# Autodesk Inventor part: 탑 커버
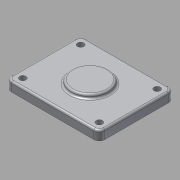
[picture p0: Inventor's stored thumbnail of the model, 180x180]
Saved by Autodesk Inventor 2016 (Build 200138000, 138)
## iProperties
Created: 2017-05
Part Number: 탑 커버
Material: 알루미늄 6061
Document SubType Name: Modeling
Designer: mduedu
Density: 1 g/cm^3
Appearance: 알루미늄 - 평지
Author: mduedu
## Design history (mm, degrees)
sketch "스케치1"
  geometry: L1 (25, 20)-(-25, 20); L2 (-25, 20)-(-25, -20); L3 (-25, -20)-(25, -20); L4 (25, -20)-(25, 20); L5 (25, 20)-(-25, -20); L6 (-25, 20)-(25, -20); 1 further point
  constraints: 12 end point, 2 midpoint, 2 parallel, 1 horizontal, 1 perpendicular
  dimensions: "d0" = 50 distance of L3.end L2.end; "d1" = 40 distance of L2.end L1.end
extrude "돌출1" new body sketch "스케치1" distance "d2" = 5; taper "d3" = 0 deg
fillet "모깎기1" dims "d4" = 3
sketch "스케치2"
  geometry: C1 r 10 at (0, 0); 1 further point
  constraints: 1 centre point, 1 coincident
  dimensions: "d5" = 20 diameter of C1
extrude "돌출2" join sketch "스케치2" distance "d6" = 2; taper "d7" = 0 deg
sketch "스케치3"
  geometry: L1 (-16, -11)-(16, -11); L2 (16, -11)-(16, 11); L3 (16, 11)-(-16, 11); L4 (-16, 11)-(-16, -11); L5 (-16, -11)-(16, 11); L6 (16, -11)-(-16, 11); 1 further point
  constraints: 12 end point, 2 midpoint, 2 parallel, 1 horizontal, 1 perpendicular
  dimensions: "d8" = 32 distance of L3.end L2.end; "d9" = 22 distance of L2.end L1.end
extrude "돌출3" join sketch "스케치3" distance "d10" = 3; taper "d11" = 0 deg
fillet "모깎기2" dims "d12" = 3
sketch "스케치4"
  geometry: L1 (-13, -11)-(13, -11) reference; L2 (16, -8)-(16, 8) reference; L3 (13, 11)-(-13, 11) reference; L4 (-16, 8)-(-16, -8) reference; L5 (-13, 9)-(13, 9); L6 (14, 8)-(14, -8); L7 (13, -9)-(-13, -9); L8 (-14, -8)-(-14, 8); A1 r 3 centre (-13, -8) between (-16, -8) and (-13, -11) reference; A2 r 3 centre (13, -8) between (13, -11) and (16, -8) reference; A3 r 3 centre (13, 8) between (16, 8) and (13, 11) reference; A4 r 3 centre (-13, 8) between (-13, 11) and (-16, 8) reference; A5 r 1 centre (13, 8) between (14, 8) and (13, 9); A6 r 1 centre (13, -8) between (13, -9) and (14, -8); A7 r 1 centre (-13, -8) between (-14, -8) and (-13, -9); A8 r 1 centre (-13, 8) between (-13, 9) and (-14, 8); 1 further point
  constraints: 8 end point, 8 point on circle, 4 centre point, 7 other
  dimensions: "d13" = 2 distance between parallel lines of L5 L3
extrude "돌출4" cut sketch "스케치4" stored distance "d14" = 2; taper "d15" = 0 deg
chamfer "모따기1" distance "d16" = 1; stored, may be unused: second distance "d17" = 2, angle "d18" = 45 deg
fillet "모깎기3" dims "d19" = 1
fillet "모깎기4" dims "d20" = 1
fillet "모깎기5" dims "d21" = 1
sketch "스케치5"
  geometry: L1 (-20.5, -15.5)-(20.5, -15.5); L2 (20.5, -15.5)-(20.5, 15.5); L3 (20.5, 15.5)-(-20.5, 15.5); L4 (-20.5, 15.5)-(-20.5, -15.5); L5 (-20.5, -15.5)-(20.5, 15.5); L6 (20.5, -15.5)-(-20.5, 15.5); L7 (22, 20)-(-22, 20) reference; L8 (25, -17)-(25, 17) reference; 5 further points
  constraints: 12 end point, 4 coincident, 2 midpoint, 2 parallel, 1 horizontal, 1 perpendicular
  dimensions: "d22" = 4.5 distance between parallel lines of L3 L7; "d23" = 4.5 distance between parallel lines of L2 L8
sketch "스케치6"
  geometry: 4 further points
  constraints: 4 other
hole "구멍1" sketch "스케치6" at (-20.5, 15.5), (20.5, 15.5), (20.5, -15.5), (-20.5, -15.5) diameter "d24" = 3.4; stored, may be unused: countersink angle "d28" = 90 deg, drill point angle "d30" = 0 deg; dims "d25" = 6, "d26" = 4, "d27" = 2, "d29" = 8
node "솔리드1"
node "투영된 루프1"
